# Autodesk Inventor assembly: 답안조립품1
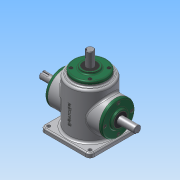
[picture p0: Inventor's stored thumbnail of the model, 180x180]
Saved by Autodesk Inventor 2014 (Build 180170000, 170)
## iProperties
Created: 2015-10
Part Number: 답안조립품1
Document SubType Name: Assembly
Designer: net
Author: net
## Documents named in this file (14)
- C:\Users\net\Desktop\451007v1028\답안조립품1.iam
- C:\Users\net\Desktop\451007v1028\본체.ipt
- C:\Users\net\Desktop\451007v1028\커버.ipt
- C:\Users\net\Desktop\451007v1028\메인 축.ipt
- 메인 축.ipt
- C:\Users\net\Desktop\451007v1028\오일실.ipt
- C:\Users\net\Desktop\451007v1028\베어링 6203.ipt
- C:\Users\net\Desktop\451007v1028\서브 축.ipt
- 서브 축.ipt
- C:\Users\net\Desktop\451007v1028\서브 베벨기어.ipt
- C:\Users\net\Desktop\451007v1028\키 4x4.ipt
- C:\Users\net\Desktop\451007v1028\키 5x5.ipt
- C:\Users\net\Desktop\451007v1028\메인 베벨기어.ipt
- C:\Users\net\Desktop\451007v1028\M4.ipt
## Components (12 placed, 1 different names)
1. M4:1
2. M4:2
3. M4:3
4. M4:4
5. M4:5
6. M4:6
7. M4:7
8. M4:8
9. M4:9
10. M4:10
11. M4:11
12. M4:12
